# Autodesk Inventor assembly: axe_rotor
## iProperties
Created: 2011-01
Part Number: axe_rotor
Document SubType Name: Assembly
Designer: eric
Mass: 3.04004 g
Surface Area: 22.1589 cm^2
Volume: 3.04004 cm^3
Density: 1 g/cm^3
Norme de conversion: IGES 5.3
Nom du fichier: No Iges File Name specified
Préprocesseur: Autodesk Inventor 2011
Postprocesseur: Build: 342, Release: 2008 SP3 - Date: Tue 05/27/2008
Unités envoyées: MM
Incertitude: 0.01
Author: eric
